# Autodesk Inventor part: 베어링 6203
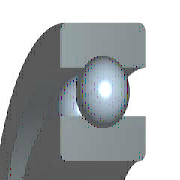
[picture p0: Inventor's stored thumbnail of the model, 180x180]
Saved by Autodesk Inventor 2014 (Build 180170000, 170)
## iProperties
IsCustomPart: 0
Company: 한국ATC센터
Created: 2014-10
Part Number: 베어링 6203
Material: Steel, Mild
Description: 깊은 그루브 볼 베어링
Document SubType Name: Modeling
Standard: KS B 2023
Designer: KYOUNG IL JANG
Standards Organization: KS
Language: ko-KR
Size Designation: 6203 - 17 x 40 x 12
Categories: <MemberInstance><Categories><Category DisplayName="샤프트 부품" InternalName="7f7aeb1f-a693-4053-b835-cee3144e0d98" Mnemonic="SHFT"><Category DisplayName="베어링" Inter
Density: 7.86 g/cm^3
Mass: 64.9809 g
Surface Area: 64.3582 cm^2
Volume: 8.26729 cm^3
Appearance: Steel - Polished
Author: KYOUNG IL JANG
Revision Number: 1
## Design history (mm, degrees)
revolve "본체" stored, may be unused: angle "d6" = 90 deg
revolve "볼" stored, may be unused: angle "d7" = 90 deg
pattern_circular "IDS_ARRAYBALL[SIMPL:T]" dims angle "d3" = 360 deg
body "Solid1"
sketch "스케치" dims "d0" = 5.98 (= -0.26 x WD + 0.26 x BD)
  geometry: L1 (3.01, 14.25)-(8.99, 14.25); L2 (6, 14.25)-(6, 11.26); L3 (6, 14.25)-(6, 17.24); L4 (3.778, 12.249)-(0, 12.249); L5 (0, 8.5)-(12, 8.5); L6 (3.778, 16.251)-(0, 16.251); L7 (0, 20)-(12, 20); L8 (12, 8.5)-(12, 12.249); L9 (8.222, 12.249)-(12, 12.249); L10 (8.222, 16.251)-(12, 16.251); L11 (12, 20)-(12, 16.251); L12 (-1.4, 0)-(8.4, 0) reference; L13 (0, -0.3)-(0, 5.3) reference
  constraints: 22 end point, 4 point on line, 2 collinear, 2 perpendicular, 2 symmetric about line, 1 midpoint, 1 parallel, 14 other
  dimensions: "d9" = 17 diameter of L5 L12 (= WD); "d11" = 40 diameter of L7 L12 (= BD); "d12" = 12 distance between parallel lines of L8 L13 (= KB); "d13" = 24.498 diameter of L9 L12 (= 0.326 x BD + 0.674 x WD)
fillet "모깎기1" dims "d1" = 0.6 (= KRS)
other parameters: "WD" = 17 [user parameter; used in 5 equation terms], "BD" = 40 [user parameter; used in 5 equation terms], "KB" = 12 [user parameter; used in 1 equation term], "KRS" = 0.6 [user parameter; used in 1 equation term], "d4" = 0, "d5" = 0, "d8" = 0, "d14" = 0, "d15" = 0, "BBA" = 0 [user parameter], "BC0" = 4750000 [user parameter], "BC" = 9560000 [user parameter], "WR" = 8.5 (= 0.5 x WD) [user parameter]
